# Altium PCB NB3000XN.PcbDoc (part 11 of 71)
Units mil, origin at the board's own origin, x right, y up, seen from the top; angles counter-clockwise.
Board outline 9527.56 x 6929.77 mil, 6 copper layers (Top Layer, GND+SHIELD, MidLayer1, MidLayer2, P2 - 3V3+5V0, Bottom Layer), stack 62.375 mil thick; 832 components, 1027 nets, 4655 pads, 4981 vias.
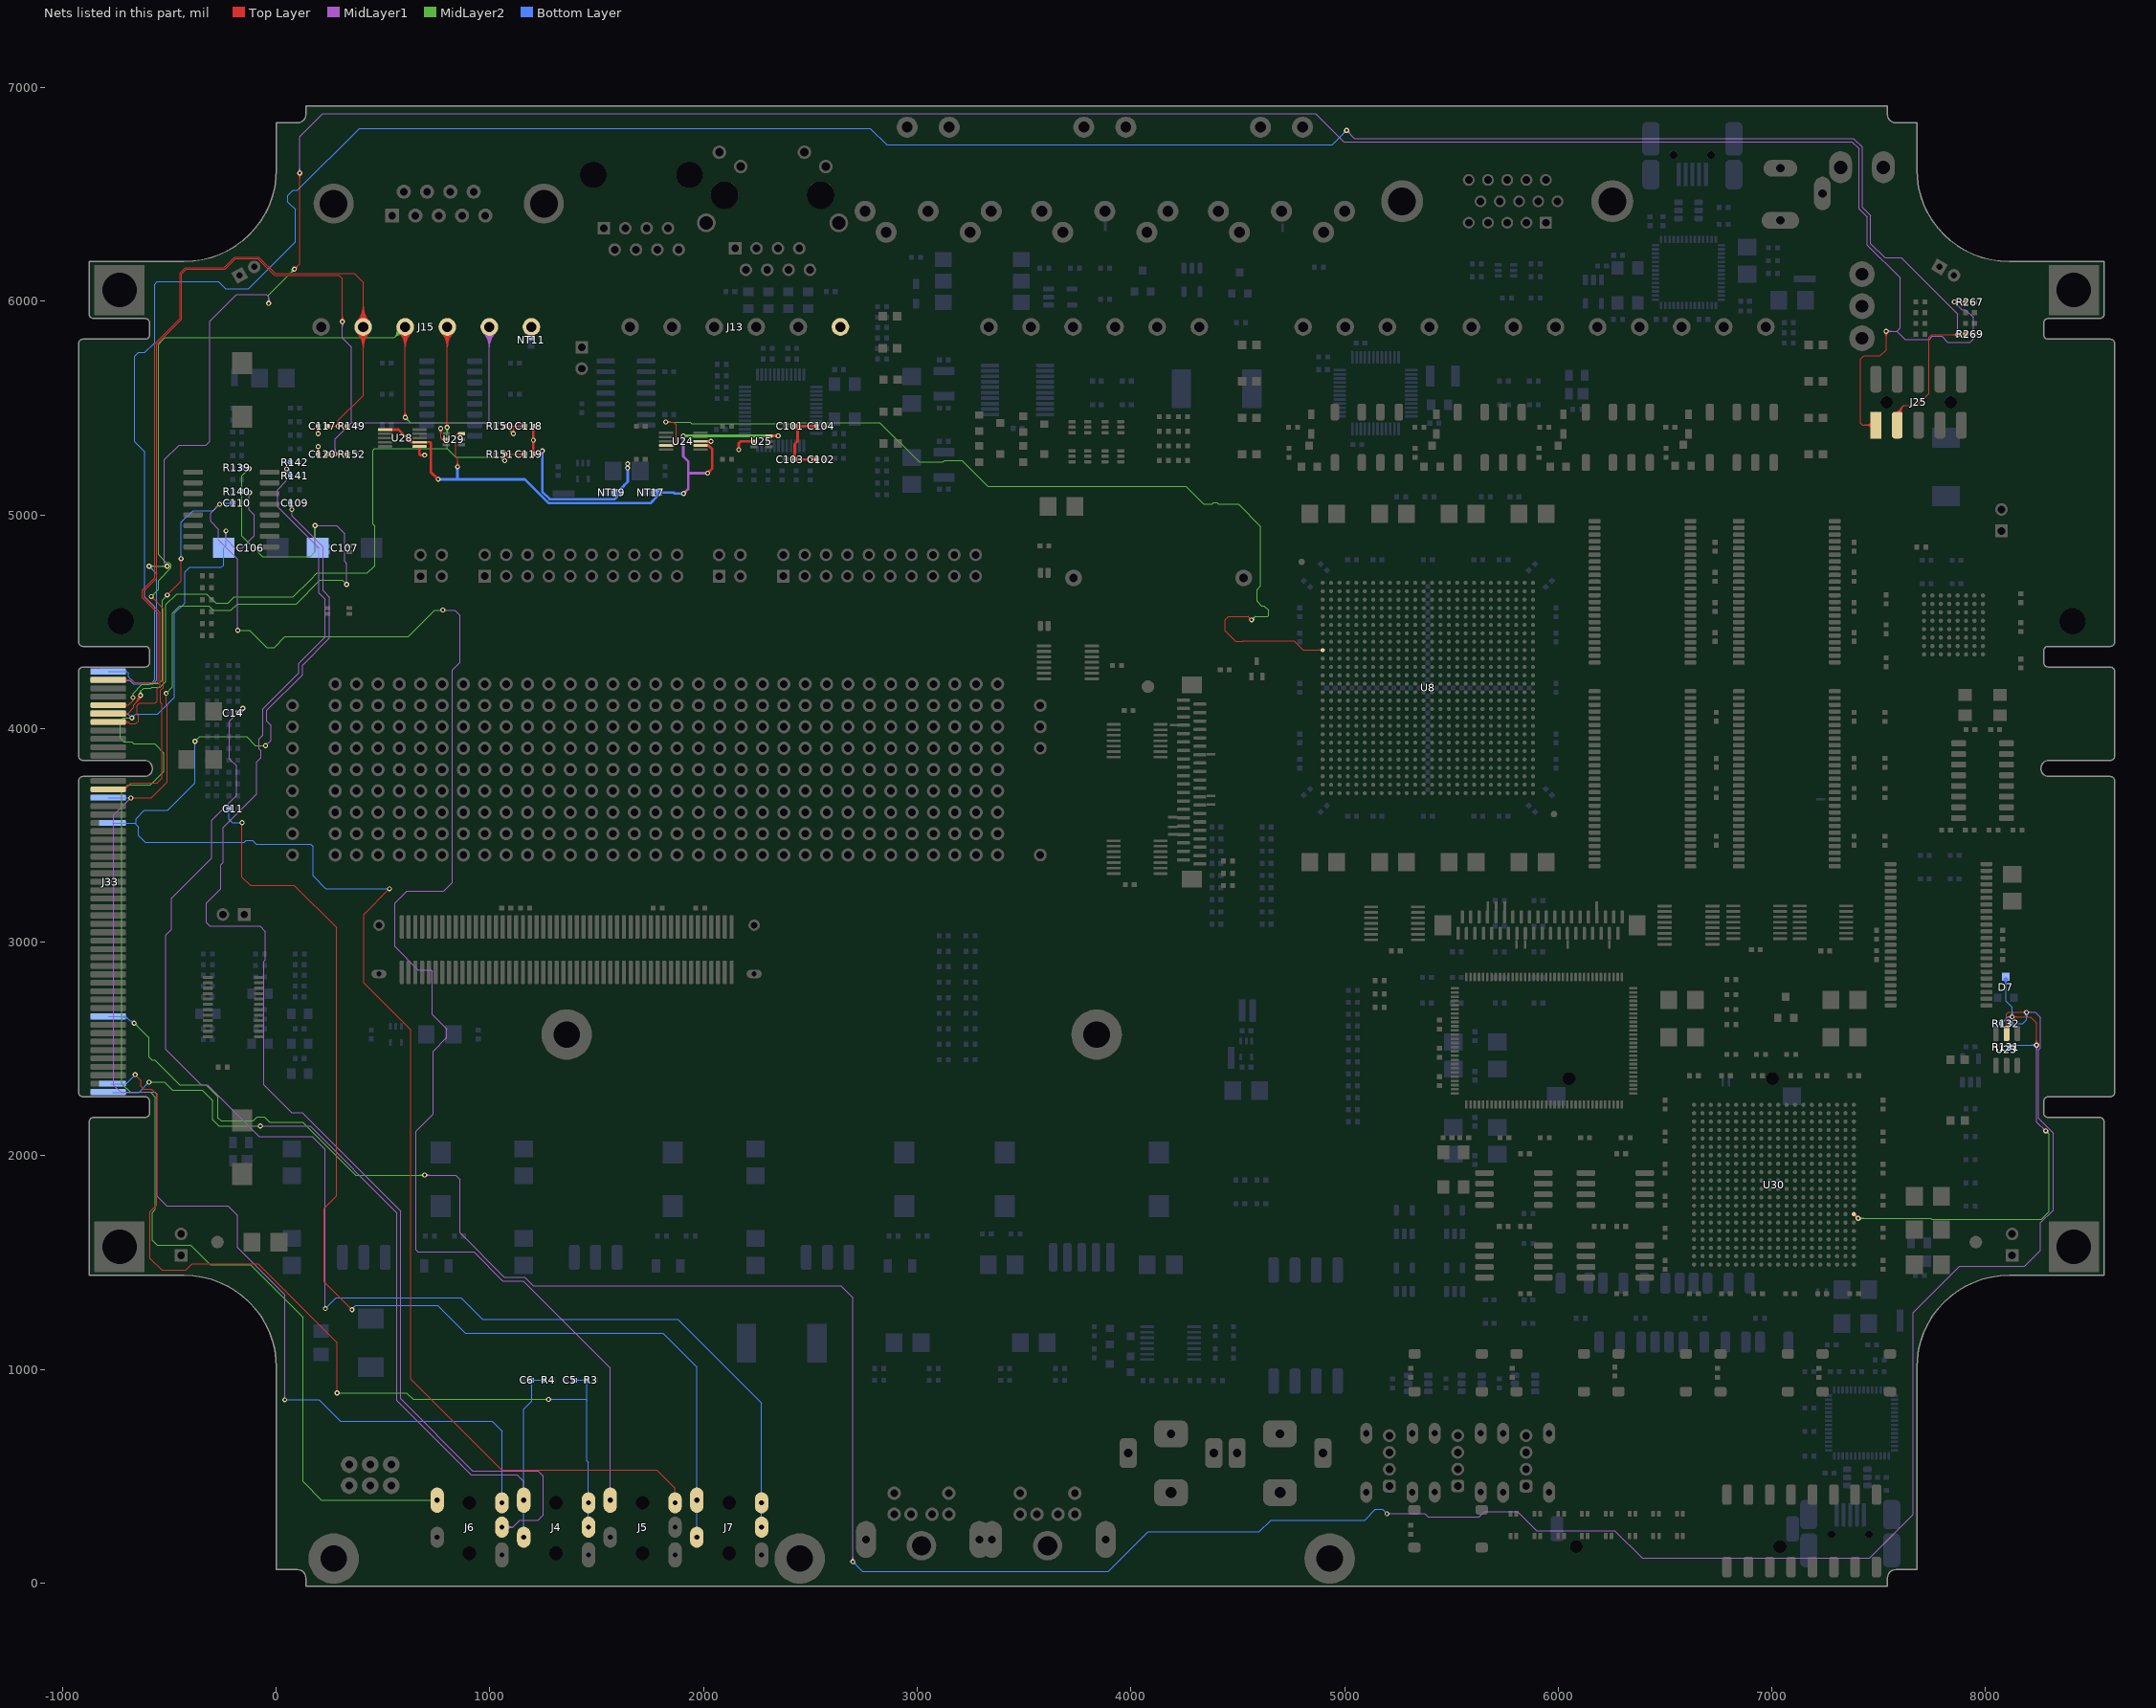
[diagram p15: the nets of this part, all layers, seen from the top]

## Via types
v1: diameter 23, hole 11.81, Top Layer to Bottom Layer, 3672 vias
v2: diameter 26, hole 11.81, Top Layer to Bottom Layer, 461 vias
v3: diameter 19, hole 11.81, Top Layer to Bottom Layer, tented both sides, 396 vias
v4: diameter 23.62, hole 11.81, Top Layer to Bottom Layer, 288 vias
v5: diameter 20, hole 11.81, Top Layer to Bottom Layer, 91 vias
v6: diameter 23, hole 11.81, Top Layer to Bottom Layer, tented both sides, 50 vias
v7: diameter 31, hole 11.81, Top Layer to Bottom Layer, 15 vias
v8: diameter 27.56, hole 11.81, Top Layer to Bottom Layer, tented both sides, 4 vias
v9: diameter 29, hole 11.81, Top Layer to Bottom Layer, 3 vias
v10: diameter 21, hole 11.81, Top Layer to Bottom Layer, 1 vias

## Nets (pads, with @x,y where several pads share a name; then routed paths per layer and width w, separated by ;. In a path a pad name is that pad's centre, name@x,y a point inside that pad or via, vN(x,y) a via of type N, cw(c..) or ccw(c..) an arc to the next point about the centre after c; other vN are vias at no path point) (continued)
ADC.DOUT: U8.J1 U24.9 | length 4725.1
  Top Layer w4: v1(1823.52,5435.04) 1858.15,5435.04 1873.52,5419.67 1873.52,5335.31 1863.52,5325.31 U24.9@1824.29,5325.31 ; v1@1827.41,5431.15 cw(c1836.8,5421.76) 1836.8,5435.04 cw(c1836.8,5448.32) v1@1827.41,5438.93 ; v1@1830.24,5428.32 cw(c1846.46,5412.11) 1846.46,5435.04 cw(c1846.46,5457.98) v1@1830.24,5441.76 ; U24.9@1854.58,5322.49 cw(c1861.41,5315.66) 1861.41,5325.31 cw(c1861.41,5334.97) U24.9@1854.58,5328.14 ; v1@4555.69,4508.37 ccw(c4532.76,4508.37) 4548.97,4524.59 ccw(c4565.19,4540.81) v1@4565.19,4517.87 ; v1@4559.69,4508.37 ccw(c4546.41,4508.37) 4555.8,4517.76 ccw(c4565.19,4527.15) v1@4565.19,4513.87 ; v1(4565.19,4508.37) 4548.52,4525.04 4456.86,4525.04 4440.19,4508.37 4440.19,4458.37 4491.19,4407.37 4522.86,4407.37 4523.52,4408.04 4525.35,4409.87 4764.07,4409.87 4806.78,4367.17 4860,4367.17 4870,4367.17 U8.J1@4897.87,4367.17 ; U8.J1@4892.57,4361.86 ccw(c4879.77,4349.06) 4879.77,4367.17 ccw(c4879.77,4385.27) U8.J1@4892.57,4372.47 ; U8.J1@4892.68,4361.97 ccw(c4880.15,4349.44) 4880.15,4367.17 ccw(c4880.15,4384.89) U8.J1@4892.68,4372.36
  MidLayer2 w4: v1@1823.52,5433.37 v1(1823.52,5435.04) 1937.77,5435.04 1945,5427.81 2444.72,5427.81 2449.45,5432.54 2824.97,5432.54 3010.51,5247 3120.29,5247 3128.29,5255 3210,5255 3331.63,5133.37 4256.86,5133.37 4340.19,5050.04 4380.29,5050.04 4387.75,5057.5 4402.25,5057.5 4409.71,5050.04 4503.65,5050.04 4606.86,4946.83 4606.86,4667.71 4590.19,4651.04 4590.19,4597.37 4612.52,4575.04 4623.52,4575.04 4645.19,4553.37 4645.19,4530.23 4640,4525.04 4581.86,4525.04 v1(4565.19,4508.37) ; v1@1827.41,5431.15 cw(c1836.8,5421.76) 1836.8,5435.04 cw(c1836.8,5448.32) v1@1827.41,5438.93 ; v1@1830.24,5428.32 cw(c1846.46,5412.11) 1846.46,5435.04 cw(c1846.46,5457.98) v1@1830.24,5441.76 ; v1@4565.19,4513.87 ccw(c4565.19,4527.15) 4574.58,4517.76 ccw(c4583.97,4508.37) v1@4570.69,4508.37 ; v1@4565.19,4517.87 ccw(c4565.19,4540.81) 4581.41,4524.59 ccw(c4597.63,4508.37) v1@4574.69,4508.37
ADCDAC_3V3: NT17.1 U24.2 U25.6 U28.1 U28.7 U29.6 | length 3378
  Top Layer w4: v1@841.81,5231.76 ccw(c825.59,5247.98) 848.52,5247.98 ccw(c871.46,5247.98) v1@855.24,5231.76 ; v1@844.64,5228.93 ccw(c835.25,5238.32) 848.52,5238.32 ccw(c861.8,5238.32) v1@852.41,5228.93 ; v1(848.52,5225.04) 848.52,5266.67 840.19,5275 840.19,5372 848.19,5380 ; U29.6@854.04,5376.81 ccw(c848.19,5373.03) 848.19,5380 ; U29.6@854.04,5383.19 cw(c848.19,5386.96) 848.19,5380 ; U29.6@867.83,5380 848.19,5380
  Top Layer w12: U28.1@509.29,5399.37 572.8,5399.37 631.86,5340.31 U28.7@670.71,5340.31 719.69,5340.31 723.52,5336.48 723.52,5201.04 v1(757.86,5166.71) ; 623.81,5348.37 ccw(c643.24,5367.81) U28.7@643.24,5340.32 ; v1@752.36,5166.71 ccw(c739.08,5166.71) 748.47,5176.1 ccw(c757.86,5185.49) v1@757.86,5172.21 ; U24.2@1985.71,5325.31 2023.84,5325.31 2040,5309.15 2040,5216.52 v1(2019.19,5195.71) ; v1@2019.19,5201.21 ccw(c2019.19,5214.49) 2028.58,5205.1 ccw(c2037.97,5195.71) v1@2024.69,5195.71 ; 2029.17,5319.98 ccw(c2015.84,5306.65) 2013.17,5325.31 cw(c2013.17,5299.56) 2031.38,5317.77 ; U25.6@2307.83,5370 v4(2350,5370) ; v4@2345.89,5365.89 ccw(c2335.97,5355.97) 2335.97,5370 ccw(c2335.97,5384.03) v4@2345.89,5374.11
  MidLayer1 w12: v4@1900.89,5365.89 cw(c1890.97,5355.97) 1905,5355.97 cw(c1919.03,5355.97) v4@1909.11,5365.89 ; v4(1905,5370) 1905,5273.97 1928.36,5250.61 1928.36,5121.54 v1(1906.86,5100.04) ; v1@1906.86,5105.54 ccw(c1906.86,5118.82) 1916.25,5109.43 ccw(c1925.64,5100.04) v1@1912.36,5100.04 ; 1929.06,5195.71 v1(2019.19,5195.71) ; v1@2015.3,5191.82 ccw(c2005.91,5182.43) 2005.91,5195.71 ccw(c2005.91,5208.99) v1@2015.3,5199.6
  MidLayer2 w12: v4(1905,5370) v4(2350,5370) ; v4@1909.11,5365.89 cw(c1919.03,5355.97) 1919.03,5370 cw(c1919.03,5384.03) v4@1909.11,5374.11 ; v4@2345.89,5365.89 ccw(c2335.97,5355.97) 2335.97,5370 ccw(c2335.97,5384.03) v4@2345.89,5374.11
  Bottom Layer w12: v1(757.86,5166.71) 848.52,5166.71 ; v1@761.75,5162.82 cw(c771.14,5153.43) 771.14,5166.71 cw(c771.14,5179.99) v1@761.75,5170.6 ; v1@844.64,5221.15 cw(c835.25,5211.76) 848.52,5211.76 cw(c861.8,5211.76) v1@852.41,5221.15 ; v1(848.52,5225.04) 848.52,5166.71 ; NT17.1@1773.56,5097.98 cw(c1760.44,5083.38) 1780.08,5083.38 ; NT17.1@1786.59,5097.98 ccw(c1799.72,5083.38) 1780.08,5083.38 ; NT17.1@1797.22,5098.34 cw(c1813.86,5081.7) 1813.86,5105.24 cw(c1813.86,5128.77) NT17.1@1797.22,5112.13 ; v1@1902.97,5096.15 ccw(c1893.58,5086.76) 1893.58,5100.04 ccw(c1893.58,5113.32) v1@1902.97,5103.93 ; v1(1906.86,5100.04) 1864.96,5100.04 1859.76,5105.24 NT17.1@1780.08,5105.24 1780.08,5083.37 ; 848.52,5166.71 1163.29,5166.71 1275,5055 1751.7,5055 1780.08,5083.37
AGND: C101.2 C102.2 C103.2 C104.2 C117.2 C118.2 C119.2 C120.2 J13.6 J15.6 NT11.1 NT19.1 U24.3 U25.2 U28.6 U29.2 | length 2383.2
  Top Layer w4: C120.2@189.39,5291.94 ccw(c172.64,5308.69) 196.33,5308.69 ccw(c220.02,5308.68) C120.2@203.27,5291.94 ; C117.2@189.39,5408.06 cw(c172.64,5391.31) 196.33,5391.31 cw(c220.02,5391.32) C117.2@203.27,5408.06 ; v1@189.61,5313.28 cw(c173.4,5297.06) 196.33,5297.06 cw(c219.27,5297.06) v1@203.05,5313.28 ; v1@189.61,5386.72 ccw(c173.4,5402.93) 196.33,5402.93 ccw(c219.27,5402.93) v1@203.05,5386.72 ; C120.2@192.22,5289.11 ccw(c182.3,5299.03) 196.33,5299.03 ccw(c210.36,5299.03) C120.2@200.44,5289.11 ; C117.2@192.22,5410.89 cw(c182.3,5400.97) 196.33,5400.97 cw(c210.36,5400.97) C117.2@200.44,5410.89 ; v1@192.44,5316.11 cw(c183.05,5306.72) 196.33,5306.72 cw(c209.61,5306.72) v1@200.22,5316.11 ; v1@192.44,5383.89 ccw(c183.05,5393.28) 196.33,5393.28 ccw(c209.61,5393.28) v1@200.22,5383.89 ; C120.2@196.33,5285 v1(196.33,5320) ; v1(196.33,5380) C117.2@196.33,5415 ; v1@763.28,5398.28 cw(c747.06,5382.06) 770,5382.06 cw(c792.93,5382.06) v1@776.72,5398.28 ; v1@766.11,5401.11 cw(c756.72,5391.72) 770,5391.72 cw(c783.28,5391.72) v1@773.89,5401.11 ; v1(770,5405) 770,5360 775.59,5354.41 ; U29.2@780.19,5354.41 U29.2@795,5354.41 775.59,5354.41 ; U29.2@781.15,5351.32 ccw(c775.59,5347.87) 775.59,5354.41 ; U29.2@781.15,5357.5 cw(c775.59,5360.95) 775.59,5354.41 ; C104.2@2530.2,5415 C104.2@2531.86,5416.66
  Top Layer w12: U28.6@670.71,5320.63 670.71,5304.29 670.71,5284.29 675,5280 v1(695,5280) ; v1@691.11,5276.11 ccw(c681.72,5266.72) 681.72,5280 ccw(c681.72,5293.28) v1@691.11,5283.89 ; C119.2@1199.56,5289.11 ccw(c1189.64,5299.03) 1203.67,5299.03 ccw(c1217.7,5299.03) 1207.78,5289.11 ccw(c1217.7,5299.03) 1217.7,5285 ccw(c1217.7,5270.97) C119.2@1207.78,5280.89 ; C118.2@1199.56,5410.89 cw(c1189.64,5400.97) 1203.67,5400.97 cw(c1217.7,5400.97) C118.2@1207.78,5410.89 ; C118.2@1203.67,5415 C119.2@1203.67,5285 1230.48,5285 v1(1245.52,5300.04) ; U24.3@1985.71,5345 v4(2035,5345) ; v4@2030.89,5340.89 ccw(c2020.97,5330.97) 2020.97,5345 ccw(c2020.97,5359.03) v4@2030.89,5349.11 ; v1@2161.11,5308.89 ccw(c2151.72,5318.28) 2165,5318.28 ccw(c2178.28,5318.28) v1@2168.89,5308.89 ; v1(2165,5305) 2165,5335 2174.41,5344.41 U25.2@2235,5344.41 ; C103.2@2425,5260 2425.19,5259.81 C103.2@2426.54,5259.81 ; C103.2@2430.64,5255.89 cw(c2440.1,5246.43) 2440.1,5259.81 ; C103.2@2430.64,5264.11 ccw(c2441.02,5274.49) 2441.02,5259.81 ; C101.2@2430.64,5410.89 cw(c2440.56,5400.97) 2440.56,5415 cw(c2440.56,5429.03) C101.2@2430.64,5419.11 ; v1@2495.92,5255.92 ccw(c2486.53,5246.53) 2486.53,5259.81 ccw(c2486.53,5273.09) v1@2495.92,5263.7 ; v1(2499.81,5259.81) C103.2@2426.54,5259.81 ; v1@2499.81,5260 C102.2@2530.2,5260 ; v1@2503.7,5255.92 cw(c2513.55,5246.07) 2513.55,5260 ; v1@2503.7,5263.7 ccw(c2512.63,5272.63) 2512.63,5260 ; C102.2@2526.09,5255.89 ccw(c2516.17,5245.97) 2516.17,5260 ccw(c2516.17,5274.03) C102.2@2526.09,5264.11 ; C104.2@2526.09,5410.89 ccw(c2516.17,5400.97) 2516.17,5415 ccw(c2516.17,5429.03) C104.2@2526.09,5419.11 ; C104.2@2530.2,5415 C101.2@2426.54,5415 2426.54,5411.54 2440,5398.07 2440,5345 2426.54,5331.54 C103.2@2426.54,5260 C103.2@2426.54,5259.81
  Bottom Layer w4: v1@690,5275 v1(695,5280)
  Bottom Layer w12: v1@1241.64,5296.15 cw(c1232.25,5286.76) 1245.52,5286.76 cw(c1258.8,5286.76) v1@1249.41,5296.15 ; v1(1245.52,5300.04) 1245.52,5108.49 1280,5074.02 1583.97,5074.02 1595.08,5085.12 ; NT19.1@1589.04,5097.59 cw(c1579.2,5085.12) 1595.08,5085.12 ; NT19.1@1601.12,5097.59 ccw(c1610.96,5085.12) 1595.08,5085.12 ; NT19.1@1615.08,5105.24 cw(c1663.36,5105.24) 1629.22,5139.38 ; v1@1640.92,5215.92 cw(c1631.07,5206.07) 1645,5206.07 ; v1@1640.92,5223.7 ccw(c1631.07,5233.55) v1@1645,5233.55 ; v1@1640.92,5235.92 cw(c1631.07,5226.07) v1@1645,5226.07 ; 1645,5206.99 cw(c1657.63,5206.99) v1@1648.7,5215.92 ; v1@1645,5226.99 cw(c1657.63,5226.99) v1@1648.7,5235.92 ; v1@1645,5232.63 ccw(c1657.63,5232.63) v1@1648.7,5223.7 ; v1@1645,5240 1645,5239.81 1645,5219.81 1645,5155.16 NT19.1@1595.08,5105.24 1595.08,5085.12
  other v1: 1644.81,5219.81 1644.81,5239.81 1203.67,5350
ATE.AUDIO.AMP_L: C11.2 J7.2 J7.10 | length 5317.2
  Top Layer w4: v1(-159.81,3559.86) -159.81,3305 -121.52,3266.71 83.29,3266.71 281.86,3068.14 281.86,1811.92 225,1755.06 225,1410 v1(355,1280)
  Bottom Layer w4: C11.2@-220.67,3625 -220.67,3574.71 -205.82,3559.86 v1(-159.81,3559.86) ; v1(355,1280) 355,1283.15 371.8,1299.95 755.05,1299.95 885,1170 1810,1170 1968.43,1011.57 J7.2@1968.43,388.03 J7.10@1968.43,214.8
ATE.AUDIO.AMP_R: C14.2 J7.3 J7.11 | length 6360.2
  MidLayer1 w4: v1(-156.5,4095) -218.14,4033.36 -218.14,3858.14 -185,3825 -185,3686.31 -301.31,3570 -301.31,3394.95 -490,3206.26 -490,3060 -517.69,3032.31 -517.69,2499.07 -350.34,2331.71 -321.71,2331.71 -80.92,2090.92 ; -80.88,2090.92 169.08,2090.92 230,2030 v1(230,1285)
  Bottom Layer w4: C14.2@-179.33,4073.18 -165,4073.18 ; C14.2@-170.18,4069.63 cw(c-165,4067.62) -165,4073.18 ; C14.2@-170.18,4076.73 ccw(c-165,4078.74) -165,4073.18 ; v1(-156.5,4095) -156.5,4081.68 -165,4073.18 ; v1(230,1285) 280,1335 865,1335 965,1235 1880,1235 2271.57,843.43 J7.3@2271.57,376.22 J7.11@2271.57,262.05
ATE.AUDIO.HP_L: C106.2 J6.2 J33.B6 R140.2 | length 7029.9
  MidLayer1 w4: v1(-235,4925) -235,4887.05 -193.47,4845.52 -159.48,4845.52 -101.48,4903.52 -101.48,5000 -126.48,5025 -126.48,5103.52 v1(-125,5105)
  MidLayer2 w4: v1@-678.57,4053.56 v1(-675,4050) -715,4050 -730,4035 -730,3955 -713.88,3938.88 -676.12,3938.88 -666.29,3929.04 -569.04,3929.04 -525,3885 -525,3800 -588,3737 -693,3737 -723,3707 -723,2338 -683,2298 -588,2298 -565,2275 -565,1750 -580,1735 -580,1605 -556.59,1581.59 -399.97,1581.59 -308.38,1490 -120,1490 125,1245 125,475 211.97,388.03 J6.2@753.43,388.03
  Bottom Layer w4: J33.B6@-785.98,4070.18 -695.18,4070.18 v1(-675,4050) -657.69,4067.31 -630,4067.31 ; -648.5,4067.31 -630,4067.31 ; C106.2@-243.14,4848.04 C106.2@-245.91,4845.28 ; v1(-235,4925) -235,4856.18 C106.2@-245.91,4845.28 ; R140.2@-160.85,5110.08 -142.85,5110.08 -136.81,5104.04 -125.96,5104.04 v1(-125,5105) ; -630,4067.31 -555.31,4067.31 -476.5,4146.12 -476.5,4540 -428,4588.5 -428,4732 -405,4755 -255.91,4755 -245.91,4765 C106.2@-245.91,4845.28
ATE.AUDIO.HP_R: C107.2 J6.3 J33.B14 R139.2 | length 8265.3
  Top Layer w4: v1(-680,3675) -584.81,3675 -560.98,3698.83 ; -564.38,3695.43 -510,3749.81 -510,3795 ; v1(-515,4165) -515,4110.19 -509.81,4105 -509.81,4070.19 ; -510,4070 -509.81,4070.19 ; -509.81,3795 -509.81,4070.19
  MidLayer1 w4: v1(-680,3675) -760,3595 -760,2330 -728,2298 -568,2298 -557.02,2287.02 -557.02,1810 -512.02,1765 -225,1765 -180.09,1720.09 -180.09,1570.09 40.19,1349.81 v1(40.19,858.37) ; v1@184.4,4947.5 v1(181.86,4950.04) 281.82,4950.04 320,4911.86 320,4782.05 330,4772.05 v1(330,4675)
  MidLayer2 w4: v1(-515,4165) -484.81,4195.19 -484.81,4540.13 -451.22,4573.71 -316.19,4573.71 -295.85,4553.37 -212.19,4553.37 -181.69,4583.87 93.87,4583.87 204.5,4694.5 310.5,4694.5 v1(330,4675) ; v1(-126.48,5216.71) -160.14,5183.04 -160.14,4900.88 -64.27,4805 160,4805 181.86,4826.86 v1(181.86,4950.04)
  Bottom Layer w4: J33.B14@-785.98,3676.48 -784.5,3675 v1(-680,3675) ; R139.2@-160.85,5220.92 -130.68,5220.92 v1(-126.48,5216.71) ; v1(40.19,858.37) 200,858.37 300,758.37 1010,758.37 1056.57,711.8 J6.3@1056.57,376.22 ; v1(181.86,4950.04) 181.86,4857.51 C107.2@194.09,4845.28
ATE.AUDIO.HP_SENSE: J6.11 R141.1 R142.2 | length 6916.6
  MidLayer1 w4: v1@41.81,5208.99 cw(c25.59,5192.77) 48.52,5192.77 cw(c71.46,5192.77) v1@55.24,5208.99 ; v1@44.64,5211.82 cw(c35.25,5202.43) 48.52,5202.43 cw(c61.8,5202.43) v1@52.41,5211.82 ; v1(48.52,5215.71) 48.52,5160 6.52,5118 6.52,5037.44 200,4843.97 200,4635 230,4605 230,4429.5 147.32,4346.81 105.19,4304.69 105.19,4259.94 -62.5,4092.25 -62.5,3970 -80,3952.5 -80,3904.86 -70.14,3895 -70.14,3864.86 -91.3,3843.7 -91.3,3693.7 -248.81,3536.19 -248.81,3373.2 -259.81,3362.2 -259.81,3250.04 -326.48,3183.37 -326.48,3091.71 -309.81,3075.04 -75,3075.04 -50,3050.04 -50,2917.93 -57.5,2910.43 -57.5,2909.75 -58,2909.25 -58,2331.56 71.06,2202.5 120.43,2202.5 582.5,1740.43 582.5,862.25 919.75,525 1225,525 1250,500 1250,320 1225,295 1140,295 1107.05,262.05 ; J6.11@1056.57,262.05 1107.05,262.05 ; J6.11@1075.3,251.5 cw(c1093.36,241.33) 1093.36,262.05 cw(c1093.36,282.77) J6.11@1075.3,272.6 ; J6.11@1078.79,249.53 cw(c1100.2,237.47) 1100.2,262.05 cw(c1100.2,286.62) J6.11@1078.79,274.56 ; J6.11@1082.27,247.57 cw(c1107.05,233.62) 1107.05,262.05 ; J6.11@1082.27,276.52 ccw(c1107.05,290.48) 1107.05,262.05
  Bottom Layer w4: v1@41.81,5222.43 ccw(c23.17,5241.06) 49.52,5241.06 ; v1@44.64,5219.6 ccw(c32.83,5231.4) 49.52,5231.4 ; v1@48.52,5206.21 cw(c48.52,5183.27) 64.74,5199.49 cw(c80.96,5215.71) v1@58.02,5215.71 ; v1@48.52,5210.21 cw(c48.52,5196.93) 57.91,5206.32 cw(c67.3,5215.71) v1@54.02,5215.71 ; v1(48.52,5215.71) 66.79,5197.44 ; v1@49.52,5216.71 49.52,5243.46 51.86,5245.8 ; 49.52,5236.23 ccw(c69.04,5236.23) v1@55.24,5222.43 ; R141.1@62.8,5191.14 ccw(c59.82,5197.44) 66.79,5197.44 ; R142.2@66.28,5245.8 51.86,5245.8 ; R141.1@66.79,5182.22 66.79,5197.44 ; R141.1@70.78,5191.14 cw(c73.76,5197.44) 66.79,5197.44 ; 51.86,5245.8 cw(c51.86,5239.3) 57.78,5241.97 ccw(c51.86,5239.3) 51.86,5245.8 ; 51.86,5245.8 ccw(c51.86,5252.29) 57.78,5249.62 cw(c51.86,5252.29) 51.86,5245.8
ATE.AUDIO.LIN_L: C6.1 J4.2 J4.10 J33.B49 R4.2 | length 4242.5
  MidLayer1 w4: v1(-74.48,2139.71) 158.48,2139.71 565,1733.18 565,855 912.5,507.5 1127.5,507.5 1158.43,476.57 J4.2@1158.43,388.03
  MidLayer2 w4: v1(-595,2345) -522.62,2345 -485,2307.38 -347.38,2307.38 -297.5,2257.5 -297.5,2170 -267.21,2139.71 v1(-74.48,2139.71)
  Bottom Layer w4: -702.5,2297.5 -765,2297.5 -642.5,2297.5 v1(-595,2345) ; J4.10@1158.43,214.8 J4.2@1158.43,388.03 1158.43,815 1195.67,852.24 C6.1@1195.67,950 R4.2@1253.83,950
ATE.AUDIO.LIN_R: C5.1 J4.3 J4.11 J33.B48 R3.2 | length 4297.5
  Top Layer w4: v1(-660,2380) -633,2353 -633,2325.62 -618.88,2311.5 -585,2311.5 -560,2286.5 -560,1770 -590,1740 -590,1520 -534.71,1464.71 -422.92,1464.71 -392.62,1495 -85,1495 285,1125 v1(285,890)
  MidLayer2 w4: v1(285,890) 610,890 640,860 v1(1275,860)
  Bottom Layer w4: J33.B48@-775,2337.9 J33.B48@-766.3,2337.9 -702.1,2337.9 v1(-660,2380) ; v1(1275,860) 1448.82,860 1453.82,855 ; C5.1@1395.66,950 R3.2@1453.82,950 1453.82,855 ; J4.11@1461.57,262.05 J4.3@1461.57,376.22 1461.57,565 1453.82,572.76 1453.82,855
ATE.AUDIO.LOUT_L: C110.2 J5.2 J33.A5 | length 8411.2
  Top Layer w4: J33.A5@-785.98,4109.55 -691.71,4109.55 ; J33.A5@-711.14,4104.53 cw(c-700.33,4095.4) -700.33,4109.55 cw(c-700.33,4123.71) J33.A5@-711.14,4114.57 ; J33.A5@-708.09,4101.95 cw(c-691.71,4088.12) -691.71,4109.55 ; J33.A5@-708.09,4117.16 ccw(c-691.71,4130.99) -691.71,4109.55 ; v1(-670,4145) -670,4131.27 -691.71,4109.55 ; v1(-509.81,4625.04) -445,4689.85 v1(-445,4795)
  MidLayer1 w4: v1(-265,5050) -306.98,5008.02 -306.98,4969.35 -270.14,4932.52 -270.14,4884.01 -180,4793.86 v1(-180,4460) ; v1@785,4550 v1(780,4555) 835,4555 860,4530 860,4309.75 825,4274.75 825,3280 785.04,3240.04 612.67,3240.04 555.11,3182.48 555.11,2978.61 663.72,2870 725,2870 731.02,2863.98 731.02,2662.39 798.5,2594.92 798.5,2553.48 735.02,2490 735.02,2196.84 654,2115.82 654,1559 663,1550 925,1550 1060,1415 1155,1415 1513.55,1056.45 1563.43,1006.57 J5.2@1563.43,388.03
  MidLayer2 w4: v1(-670,4145) -670,4165 -627.96,4207.04 -592.9,4207.04 -589.63,4210.31 -550.96,4210.31 -533.48,4227.78 -533.48,4601.37 v1(-509.81,4625.04) ; v1(-180,4460) -125,4460 -45,4380 -8.33,4380 41.67,4430 617.63,4430 742.63,4555 v1(780,4555)
  Bottom Layer w4: v1(-445,4795) -445,4965 -390,5020 -295,5020 v1(-265,5050) -259.92,5055.08 C110.2@-202.7,5055.08
ATE.AUDIO.LOUT_R: C109.1 J5.3 J33.B17 | length 7821.7
  Top Layer w4: v1(530,3250) 530,3249.52 410,3129.52 410,2810 630,2590 630,955.57 1055,530.57 1780,530.57 1866.57,443.99 J5.3@1866.57,376.22
  MidLayer1 w4: v1@-45,3925 v1(-50,3920) -25,3945 -25,4015 -45,4035 -45,4085 122.69,4252.69 122.69,4297.44 250,4424.75 250,4615 220,4645 220,4848.71 73.52,4995.19 v1(73.52,5025.04)
  MidLayer2 w4: v1(-380,3940) -358.29,3961.71 -138.63,3961.71 -96.92,3920 v1(-50,3920)
  Bottom Layer w4: J33.B17@-765.61,3557.69 -658.07,3557.69 -655.76,3560 ; v1@-380,3930 -380,3745 -507,3618 -617,3618 -617,3617.35 -655.76,3578.58 -655.76,3560 ; 66.79,5040.28 ccw(c83.5,5040.28) v1@74.35,5026.3 ; C109.1@66.79,5047.68 ccw(c88.35,5047.68) v1@76.54,5029.64 ; v1(73.52,5025.04) 66.79,5031.77 C109.1@66.79,5055.08 ccw(c93.2,5055.08) v1@78.73,5032.99 ; v1@529.99,3250.04 232.15,3250.04 172,3310.19 172,3448.08 161.71,3458.37 -93.65,3458.37 -111.98,3476.71 -140.97,3476.71 -150.18,3467.5 -612.5,3467.5 -645,3500 -645,3540 -655.76,3550.76 -655.76,3560
ATE.DAC#.DAC0: C117.1 J15.2 J33.A2 R149.1 | length 5765.6
  Top Layer w4: J33.A2@-785.98,4227.66 -675.96,4227.66 -665,4216.71 -553.29,4216.71 -552,4218 -552,4538.31 -598.56,4584.87 -598.69,4584.87 -625.81,4612 -625.81,4648.33 -568.14,4706 -568.14,5800.96 -450,5919.1 -450,6133.37 -425,6158.37 -242.94,6158.37 -193.83,6207.48 -82.48,6207.48 -5,6130 365,6130 406.99,6088.01 J15.2@406.99,5880 406.99,5560 290,5443.01 v1(290,5415) ; J33.A2@-711.58,4222.16 cw(c-698.3,4208.88) -698.3,4227.66 cw(c-698.3,4246.45) J33.A2@-711.58,4233.17 ; J33.A2@-708.76,4219.33 cw(c-688.65,4199.23) -688.65,4227.66 cw(c-688.65,4256.1) J33.A2@-708.76,4235.99 ; C117.1@237.67,5415 v1(290,5415) ; C117.1@241.78,5410.89 cw(c251.7,5400.97) 251.7,5415 cw(c251.7,5429.03) C117.1@241.78,5419.11 ; C117.1@244.61,5408.06 cw(c261.36,5391.31) 261.36,5415 cw(c261.36,5438.69) C117.1@244.61,5421.94 ; R149.1@333.82,5415 v1(290,5415) ; J15.2@379.17,5852.18 cw(c312.02,5785.03) 406.99,5785.03 cw(c501.96,5785.03) J15.2@434.8,5852.18 ; J15.2@379.17,5907.82 ccw(c312.02,5974.97) 406.99,5974.97 ccw(c501.96,5974.97) J15.2@434.8,5907.82 ; J15.2@382,5855.01 cw(c321.67,5794.69) 406.99,5794.69 cw(c492.3,5794.69) J15.2@431.98,5855.01 ; J15.2@382,5904.99 ccw(c321.67,5965.31) 406.99,5965.31 ccw(c492.3,5965.31) J15.2@431.98,5904.99 ; J15.2@384.83,5857.84 cw(c331.33,5804.34) 406.99,5804.34 cw(c482.65,5804.34) J15.2@429.15,5857.84 ; J15.2@384.83,5902.16 ccw(c331.33,5955.66) 406.99,5955.66 ccw(c482.65,5955.66) J15.2@429.15,5902.16 ; J15.2@387.66,5860.67 cw(c340.99,5814) 406.99,5814 cw(c472.99,5814) J15.2@426.32,5860.67 ; J15.2@387.66,5899.33 ccw(c340.99,5946) 406.99,5946 ccw(c472.99,5946) J15.2@426.32,5899.33 ; J15.2@390.49,5863.5 cw(c350.64,5823.66) 406.99,5823.66 cw(c463.33,5823.66) J15.2@423.49,5863.5 ; J15.2@390.49,5896.5 ccw(c350.64,5936.34) 406.99,5936.34 ccw(c463.33,5936.34) J15.2@423.49,5896.5 ; J15.2@393.31,5866.33 cw(c360.3,5833.31) 406.99,5833.31 cw(c453.68,5833.31) J15.2@420.66,5866.33 ; J15.2@393.31,5893.67 ccw(c360.3,5926.69) 406.99,5926.69 ccw(c453.68,5926.69) J15.2@420.66,5893.67 ; 267.06,5415 cw(c267.06,5392.06) 283.28,5408.28 ccw(c267.06,5392.06) 267.06,5415 ; 267.06,5415 ccw(c267.06,5437.93) v1@283.28,5421.72 ; 267.06,5415 ccw(c267.06,5437.93) v1@283.28,5421.72 ; 276.72,5415 cw(c276.72,5401.72) 286.11,5411.11 ccw(c276.72,5401.72) 276.72,5415 ; 276.72,5415 ccw(c276.72,5428.28) v1@286.11,5418.89 ; 276.72,5415 ccw(c276.72,5428.28) v1@286.11,5418.89 ; v1@283.28,5421.72 ccw(c267.06,5437.93) 290,5437.93 ccw(c312.93,5437.93) v1@296.72,5421.72 ; v1@286.11,5418.89 ccw(c276.72,5428.28) 290,5428.28 ccw(c303.28,5428.28) v1@293.89,5418.89 ; v1@293.89,5418.89 ccw(c303.28,5428.28) 303.28,5415 ; v1@293.89,5418.89 ccw(c303.28,5428.28) 303.28,5415 ; v1@296.72,5421.72 ccw(c312.93,5437.93) 312.93,5415 ; v1@296.72,5421.72 ccw(c312.93,5437.93) 312.93,5415 ; 303.28,5415 ccw(c303.28,5401.72) 293.89,5411.11 cw(c303.28,5401.72) 303.28,5415 ; 312.93,5415 ccw(c312.93,5392.06) 296.72,5408.28 cw(c312.93,5392.06) 312.93,5415
ATE.DAC#.DAC1: C118.1 J15.3 J33.A13 R150.1 | length 6280.2
  Top Layer w4: J33.A13@-785.98,3715.85 -709.15,3715.85 -680,3745 -556.52,3745 -534.5,3767.02 -534.5,4115 -541,4121.5 -541,4179 -528,4192 -528,4561.56 v1(-584.81,4618.37) ; J33.A13@-717.08,3715.63 ccw(c-717.08,3734.26) J33.A13@-703.91,3721.09 ; J33.A13@-717.08,3719.63 ccw(c-717.08,3747.92) -697.08,3727.92 ; J33.A13@-717.08,3723.63 ccw(c-717.08,3761.58) -690.25,3734.75 ; J33.A13@-717.08,3727.63 ccw(c-717.08,3775.23) -683.43,3741.57 ; J33.A13@-705.3,3715.85 cw(c-696.03,3715.85) -702.59,3722.41 ; v1@-584.81,4608.87 cw(c-584.81,4585.94) -568.59,4602.16 cw(c-552.37,4618.37) v1@-575.31,4618.37 ; v1@-584.81,4612.87 cw(c-584.81,4599.6) -575.42,4608.99 cw(c-566.03,4618.37) v1@-579.31,4618.37 ; J15.3@576.02,5852.18 cw(c508.87,5785.03) 603.84,5785.03 cw(c698.81,5785.03) J15.3@631.66,5852.18 ; J15.3@578.85,5855.01 cw(c518.52,5794.69) 603.84,5794.69 cw(c689.15,5794.69) J15.3@628.83,5855.01 ; J15.3@581.68,5857.84 cw(c528.18,5804.34) 603.84,5804.34 cw(c679.5,5804.34) J15.3@626,5857.84 ; J15.3@584.51,5860.67 cw(c537.84,5814) 603.84,5814 cw(c669.84,5814) J15.3@623.17,5860.67 ; J15.3@587.34,5863.5 cw(c547.49,5823.66) 603.84,5823.66 cw(c660.18,5823.66) J15.3@620.34,5863.5 ; J15.3@590.16,5866.33 cw(c557.15,5833.31) 603.84,5833.31 cw(c650.53,5833.31) J15.3@617.51,5866.33 ; v4@596.9,5463.1 ccw(c580.15,5479.85) 603.84,5479.85 ccw(c627.52,5479.85) v4@610.78,5463.1 ; v4@599.73,5460.27 ccw(c589.81,5470.19) 603.84,5470.19 ccw(c617.87,5470.19) v4@607.95,5460.27 ; v4(603.84,5456.16) J15.3@603.84,5880 ; R150.1@1070,5415 1110,5415 ; R150.1@1073.76,5411.24 cw(c1082.84,5402.16) 1082.84,5415 cw(c1082.84,5427.84) R150.1@1073.76,5418.76 ; R150.1@1076.59,5408.41 cw(c1092.5,5392.5) 1092.5,5415 cw(c1092.5,5437.5) R150.1@1076.59,5421.59 ; v1@1103.28,5386.72 ccw(c1087.06,5402.93) 1110,5402.93 ccw(c1132.93,5402.93) v1@1116.72,5386.72 ; v1@1106.11,5383.89 ccw(c1096.72,5393.28) 1110,5393.28 ccw(c1123.28,5393.28) v1@1113.89,5383.89 ; v1(1110,5380) 1110,5415 ; C118.1@1155.39,5408.06 ccw(c1138.64,5391.31) 1138.64,5415 ccw(c1138.64,5438.69) C118.1@1155.39,5421.94 ; C118.1@1158.22,5410.89 ccw(c1148.3,5400.97) 1148.3,5415 ccw(c1148.3,5429.03) C118.1@1158.22,5419.11 ; C118.1@1162.33,5415 1110,5415
  MidLayer2 w4: v1(-584.81,4618.37) -551.48,4651.71 -551.48,4693.34 -492.19,4752.62 -492.19,4767.38 -502.62,4777.81 -516.5,4777.81 -551.48,4812.79 -551.48,5800 -521.48,5830 553.84,5830 ; v1@-584.81,4623.87 ccw(c-584.81,4637.15) -575.42,4627.76 ccw(c-566.03,4618.37) v1@-579.31,4618.37 ; v1@-584.81,4627.87 ccw(c-584.81,4650.81) -568.59,4634.59 ccw(c-552.37,4618.37) v1@-575.31,4618.37 ; J15.3@565.54,5871.03 cw(c522.81,5861.03) 553.84,5830 ; J15.3@569.43,5871.94 cw(c531.05,5862.96) 558.92,5835.09 cw(c586.8,5807.21) J15.3@595.78,5845.59 ; J15.3@573.33,5872.85 cw(c539.29,5864.89) 564.01,5840.17 cw(c588.72,5815.45) J15.3@596.69,5849.49 ; J15.3@577.22,5873.77 cw(c547.53,5866.81) 569.09,5845.25 cw(c590.65,5823.69) J15.3@597.61,5853.38 ; J15.3@581.11,5874.68 cw(c555.77,5868.74) 574.18,5850.34 cw(c592.58,5831.93) J15.3@598.52,5857.28 ; J15.3@594.87,5841.7 ccw(c584.87,5798.98) 553.84,5830 ; v4@603.84,5446.35 cw(c603.84,5422.66) 620.59,5439.41 cw(c637.34,5456.16) v4@613.65,5456.16 ; v4@603.84,5450.35 cw(c603.84,5436.32) 613.76,5446.24 cw(c623.68,5456.16) v4@609.65,5456.16 ; v4(603.84,5456.16) 627.5,5432.5 1057.49,5432.5 1063.76,5426.23 v1(1110,5380) ; J15.3@603.84,5880 553.84,5830 ; v1@1100.5,5380 ccw(c1077.56,5380) 1093.78,5396.22 ccw(c1110,5412.43) v1@1110,5389.5 ; v1@1104.5,5380 ccw(c1091.22,5380) 1100.61,5389.39 ccw(c1110,5398.78) v1@1110,5385.5
ATE.DAC#.DAC2: C119.1 J15.4 J33.A6 R151.1 | length 4976.3
  Top Layer w4: J33.A6@-785.98,4070.18 -694.82,4070.18 ; J33.A6@-710.65,4065.81 cw(c-702.38,4060.17) -702.38,4070.18 cw(c-702.38,4080.19) J33.A6@-710.65,4074.56 ; J33.A6@-707.35,4063.56 cw(c-694.82,4055.03) -694.82,4070.18 ; J33.A6@-707.35,4076.81 ccw(c-694.82,4085.34) -694.82,4070.18 ; -659.07,4117.45 ccw(c-694.34,4152.72) v1@-644.49,4154.64 ; -652.59,4123.92 ccw(c-681.87,4153.2) v1@-640.5,4154.79 ; -646.12,4130.4 ccw(c-669.4,4153.68) v1@-636.5,4154.94 ; -639.64,4136.87 ccw(c-656.93,4154.16) v1@-632.5,4155.1 ; v1(-635,4155) -635,4141.52 -665.81,4110.71 -665.81,4099.19 -694.82,4070.18 ; J15.4@772.87,5852.18 cw(c705.72,5785.03) 800.69,5785.03 cw(c895.66,5785.03) J15.4@828.51,5852.18 ; J15.4@775.7,5855.01 cw(c715.37,5794.69) 800.69,5794.69 cw(c886,5794.69) J15.4@825.68,5855.01 ; J15.4@778.53,5857.84 cw(c725.03,5804.34) 800.69,5804.34 cw(c876.35,5804.34) J15.4@822.85,5857.84 ; J15.4@781.36,5860.67 cw(c734.69,5814) 800.69,5814 cw(c866.69,5814) J15.4@820.02,5860.67 ; J15.4@784.19,5863.5 cw(c744.34,5823.66) 800.69,5823.66 cw(c857.03,5823.66) J15.4@817.19,5863.5 ; J15.4@787.01,5866.33 cw(c754,5833.31) 800.69,5833.31 cw(c847.38,5833.31) J15.4@814.36,5866.33 ; v4@793.06,5416.94 ccw(c774.65,5435.35) 800.69,5435.35 ; v4@795.89,5414.11 ccw(c784.31,5425.69) 800.69,5425.69 ; v4@800.69,5410.69 J15.4@800.69,5880 ; 800.69,5422.37 ccw(c812.37,5422.37) v4@804.11,5414.11 ; 800.69,5432.02 ccw(c822.02,5432.02) v4@806.94,5416.94 ; v1@1063.14,5260.43 ccw(c1046.58,5276.99) R151.1@1070,5276.99 ; R151.1@1063.41,5277.92 cw(c1047.5,5262.01) 1070,5262.01 cw(c1092.5,5262.01) R151.1@1076.59,5277.92 ; v1@1065.97,5257.6 ccw(c1056.23,5267.33) 1070,5267.33 ; R151.1@1066.24,5280.75 cw(c1057.16,5271.67) 1070,5271.67 cw(c1082.84,5271.67) R151.1@1073.76,5280.75 ; v1@1070,5253.71 R151.1@1070,5285 C119.1@1162.33,5285 ; 1070,5266.64 ccw(c1082.79,5266.64) v1@1073.75,5257.6 ; R151.1@1070,5276.3 ccw(c1092.45,5276.3) v1@1076.57,5260.43 ; R151.1@1073.76,5281.24 cw(c1082.84,5272.16) 1082.84,5285 cw(c1082.84,5297.84) R151.1@1073.76,5288.76 ; R151.1@1076.59,5278.41 cw(c1092.5,5262.5) 1092.5,5285 cw(c1092.5,5307.5) R151.1@1076.59,5291.59 ; C119.1@1155.39,5278.06 ccw(c1138.65,5261.31) 1138.65,5285 ccw(c1138.64,5308.69) C119.1@1155.39,5291.94 ; C119.1@1158.22,5280.89 ccw(c1148.3,5270.97) 1148.3,5285 ccw(c1148.3,5299.03) C119.1@1158.22,5289.11
  MidLayer2 w4: v1@-641.07,4162.31 ccw(c-651.83,4175.25) -635,4175.25 ; v1@-638.52,4159.23 ccw(c-644.75,4166.72) -635,4166.72 ccw(c-625.25,4166.72) v1@-631.48,4159.23 ; v1(-635,4155) -635,4175.25 ; v1@-628.93,4162.31 cw(c-618.17,4175.25) -635,4175.25 ; v4@793.06,5403.06 cw(c776.31,5386.31) 800,5386.31 cw(c823.69,5386.31) v4@806.94,5403.06 ; v4@795.89,5405.89 cw(c785.97,5395.97) 800,5395.97 cw(c814.03,5395.97) v4@804.11,5405.89 ; v4(800,5410) 800,5310 ; v1@1060.36,5253.71 ccw(c1037.42,5253.71) 1053.64,5269.93 ccw(c1069.86,5286.14) v1@1069.86,5263.21 ; v1@1064.36,5253.71 ccw(c1051.08,5253.71) 1060.47,5263.1 ccw(c1069.86,5272.49) v1@1069.86,5259.21 ; v1(1069.86,5253.71) 1053.56,5270 840,5270 800,5310 ; -635,4175.25 -620.71,4189.54 -585.65,4189.54 -582.38,4192.81 -543.71,4192.81 -515.98,4220.54 -515.98,4580.08 -465.56,4630.5 -325.6,4630.5 -281.97,4586.87 -226.26,4586.87 -195.76,4617.37 80,4617.37 160.9,4698.27 190.62,4728 426.69,4728 461.5,4762.81 461.5,4947.19 452,4956.69 452,5302 460,5310 800,5310
ATE.DAC#.DAC3: C120.1 J15.5 J33.A7 R152.1 | length 6441.9
  Top Layer w4: J33.A7@-785.98,4030.81 -691.8,4030.81 ; J33.A7@-711.13,4025.81 cw(c-700.38,4016.78) -700.38,4030.81 cw(c-700.38,4044.85) J33.A7@-711.13,4035.82 ; J33.A7@-708.07,4023.24 cw(c-691.8,4009.56) -691.8,4030.81 ; J33.A7@-708.07,4038.39 ccw(c-691.8,4052.06) -691.8,4030.81 ; -595.37,4592.87 -610.32,4607.82 -617.81,4615.31 -617.81,4645.02 -559.81,4703.02 -559.81,5797.98 -459.81,5897.98 -442,5915.79 -442,6128 -420,6150 -290,6150 -239.96,6150.04 -225,6165 -190.52,6199.48 -85.79,6199.48 -8.31,6122 293,6122 310,6105 v4(310,5905) ; -595.25,4592.87 -544,4541.63 -544,4200 -557,4187 -557,4128.5 -565,4120.5 -639,4120.5 -651,4108.5 -651,4064.87 -645,4058.87 -645,4035 -657,4023 -683.98,4023 -691.8,4030.81 ; C120.1@237.67,5285 R152.1@333.82,5285 ; C120.1@241.78,5280.89 cw(c251.7,5270.97) 251.7,5285 ; C120.1@241.78,5289.11 ccw(c251.7,5299.03) 251.7,5285 ; C120.1@244.61,5278.06 cw(c261.35,5261.31) 261.35,5285 cw(c261.36,5308.69) C120.1@244.61,5291.94 ; v1@268.28,5278.28 ccw(c252.07,5262.06) 252.06,5285 ccw(c252.06,5307.93) v1@268.28,5291.72 ; v1@271.11,5281.11 ccw(c261.72,5271.72) 261.72,5285 ccw(c261.72,5298.28) v1@271.11,5288.89 ; v1@278.89,5281.11 cw(c288.28,5271.72) 288.28,5285 cw(c288.28,5298.28) v1@278.89,5288.89 ; v1@281.72,5278.28 cw(c297.93,5262.06) 297.93,5285 cw(c297.94,5307.93) v1@281.72,5291.72 ; v4@303.06,5911.94 ccw(c286.31,5928.69) 310,5928.69 ccw(c333.69,5928.69) v4@316.94,5911.94 ; v4@305.89,5909.11 ccw(c295.97,5919.03) 310,5919.03 ccw(c324.03,5919.03) v4@314.11,5909.11 ; R152.1@327.23,5278.41 ccw(c311.32,5262.5) 311.32,5285 ccw(c311.32,5307.5) R152.1@327.23,5291.59 ; R152.1@330.06,5281.24 ccw(c320.98,5272.16) 320.98,5285 ccw(c320.98,5297.84) R152.1@330.06,5288.76
  MidLayer1 w4: v1@268.28,5291.72 ccw(c252.06,5307.93) 275,5307.93 ccw(c297.93,5307.93) v1@281.72,5291.72 ; v1@271.11,5288.89 ccw(c261.72,5298.28) 275,5298.28 ccw(c288.28,5298.28) v1@278.89,5288.89 ; v1(275,5285) 275,5355 352.5,5432.5 ; v4@303.06,5898.06 cw(c286.31,5881.31) 310,5881.31 cw(c333.69,5881.31) v4@316.94,5898.06 ; v4@305.89,5900.89 cw(c295.97,5890.97) 310,5890.97 cw(c324.03,5890.97) v4@314.11,5900.89 ; v4(310,5905) 310,5827.5 352.5,5785 352.5,5432.5 ; J15.5@969.72,5852.18 cw(c902.57,5785.03) 997.54,5785.03 cw(c1092.51,5785.03) J15.5@1025.36,5852.18 ; J15.5@972.55,5855.01 cw(c912.22,5794.69) 997.54,5794.69 cw(c1082.85,5794.69) J15.5@1022.53,5855.01 ; J15.5@975.38,5857.84 cw(c921.88,5804.34) 997.54,5804.34 cw(c1073.2,5804.34) J15.5@1019.7,5857.84 ; J15.5@978.21,5860.67 cw(c931.54,5814) 997.54,5814 cw(c1063.54,5814) J15.5@1016.87,5860.67 ; J15.5@981.04,5863.5 cw(c941.19,5823.66) 997.54,5823.66 cw(c1053.88,5823.66) J15.5@1014.04,5863.5 ; J15.5@983.86,5866.33 cw(c950.85,5833.31) 997.54,5833.31 cw(c1044.23,5833.31) J15.5@1011.21,5866.33 ; J15.5@997.54,5880 997.54,5442.54 987.5,5432.5 352.5,5432.5
ATE.HOST_ID.DATA: D7.2 R131.1 R132.2 U30.A14 | length 3141.1
  Top Layer w4: v1(8124.52,2650.04) 8209.96,2650.04 8239.19,2620.81 v1(8239.19,2518.04) ; v1@8128.41,2646.15 cw(c8137.8,2636.76) 8137.8,2650.04 cw(c8137.8,2663.32) v1@8128.41,2653.93 ; v1@8131.24,2643.32 cw(c8147.46,2627.11) 8147.46,2650.04 cw(c8147.46,2672.98) v1@8131.24,2656.76 ; v1@8232.47,2524.76 ccw(c8216.26,2540.98) 8239.19,2540.98 ccw(c8262.13,2540.98) v1@8245.91,2524.76 ; v1@8235.3,2521.93 ccw(c8225.91,2531.32) 8239.19,2531.32 ccw(c8252.47,2531.32) v1@8243.08,2521.93
  Top Layer w8: U30.A14@7384.02,1721.36 cw(c7384.02,1707.26) 7393.99,1717.23 cw(c7403.96,1727.2) U30.A14@7389.86,1727.2 ; U30.A14@7384.02,1727.2 v2(7403.7,1707.52) ; v2@7394.7,1707.52 ccw(c7372.97,1707.52) 7388.34,1722.88 ccw(c7403.7,1738.25) v2@7403.7,1716.52
  MidLayer1 w4: v1@8232.47,2511.32 cw(c8214.64,2493.5) 8239.86,2493.5 ; v1@8235.3,2514.15 cw(c8224.3,2503.15) 8239.86,2503.15 ; v1(8239.19,2518.04) 8239.86,2517.37 8239.86,2158.71 v1(8281.86,2116.71) ; 8239.86,2496.72 cw(c8260.51,2496.72) v1@8245.91,2511.32 ; 8239.86,2506.37 cw(c8250.86,2506.37) v1@8243.08,2514.15 ; v1@8272.36,2116.71 ccw(c8249.42,2116.71) 8265.64,2132.93 ccw(c8281.86,2149.14) v1@8281.86,2126.21 ; v1@8276.36,2116.71 ccw(c8263.08,2116.71) 8272.47,2126.1 ccw(c8281.86,2135.49) v1@8281.86,2122.21
  MidLayer2 w4: v2(7403.7,1707.52) 7744.11,1707.52 7748.52,1703.11 8260.92,1703.11 8297.81,1740 8297.81,2100.75 ; v2@7408.65,1702.57 cw(c7420.6,1690.62) 7420.6,1707.52 cw(c7420.6,1724.42) v2@7408.65,1712.47 ; v2@7411.48,1699.74 cw(c7430.26,1680.96) 7430.26,1707.52 cw(c7430.26,1734.08) v2@7411.48,1715.3 ; v1(8281.86,2116.71) 8297.81,2100.75 ; v1@8281.92,2111.21 cw(c8282.07,2098.45) 8291.09,2107.47 cw(c8300.12,2116.49) v1@8287.36,2116.64 ; v1@8281.97,2107.21 cw(c8282.23,2085.17) 8297.81,2100.75 ; v1@8291.36,2116.6 ccw(c8313.39,2116.34) 8297.81,2100.75
  Bottom Layer w4: R132.2@8073.82,2620 8093.05,2639.23 8103.86,2650.04 ; R132.2@8073.82,2625.81 ccw(c8073.82,2639.83) R132.2@8083.73,2629.92 ; R132.2@8073.82,2629.81 ccw(c8073.82,2653.49) 8090.56,2636.75 ; R132.2@8079.14,2620.49 cw(c8090.8,2620.49) R132.2@8082.55,2628.74 ; R132.2@8083.14,2620.49 cw(c8104.45,2620.49) 8089.38,2635.56 ; D7.2@8083.89,2826.12 cw(c8057.06,2799.28) 8095,2799.28 cw(c8132.94,2799.29) D7.2@8106.11,2826.12 ; D7.2@8086.72,2828.94 cw(c8066.71,2808.94) 8095,2808.94 cw(c8123.29,2808.94) D7.2@8103.28,2828.94 ; D7.2@8089.54,2831.77 cw(c8076.37,2818.6) 8095,2818.6 cw(c8113.63,2818.6) D7.2@8100.46,2831.77 ; D7.2@8095,2838.21 8095,2724.62 8124.52,2695.09 v1(8124.52,2650.04) 8103.86,2650.04 ; R131.1@8116.18,2510 8133.23,2510 ; v1@8117.31,2643.86 ccw(c8103.86,2632.31) 8103.86,2650.04 ; v1@8117.31,2656.23 cw(c8103.86,2667.77) 8103.86,2650.04 ; v1@8117.81,2656.76 ccw(c8101.59,2672.98) 8124.52,2672.98 ccw(c8147.46,2672.98) v1@8131.24,2656.76 ; v1@8120.35,2646.46 ccw(c8112.56,2639.78) 8112.56,2650.04 ccw(c8112.56,2660.3) v1@8120.35,2653.62 ; v1@8120.64,2653.93 ccw(c8111.25,2663.32) 8124.52,2663.32 ccw(c8137.8,2663.32) v1@8128.41,2653.93 ; R131.1@8124.02,2504.97 cw(c8133.23,2499.06) 8133.23,2510 ; R131.1@8124.02,2515.03 ccw(c8133.23,2520.94) 8133.23,2510 ; v1@8232.47,2511.32 ccw(c8216.26,2495.11) 8216.26,2518.04 ccw(c8216.26,2540.98) v1@8232.47,2524.76 ; v1@8235.3,2514.15 ccw(c8225.91,2504.76) 8225.91,2518.04 ccw(c8225.91,2531.32) v1@8235.3,2521.93 ; v1(8239.19,2518.04) 8141.27,2518.04 8133.23,2510
ATE.HOST_ID.EXT_PROG: J33.B40 R132.1 U23.2 | length 14798.7
  Top Layer w4: U23.2@8091.37,2603.08 ccw(c8072.94,2621.51) 8099,2621.51 ; U23.2@8094.19,2600.25 ccw(c8082.59,2611.85) 8099,2611.85 ccw(c8115.4,2611.85) U23.2@8103.8,2600.25 ; U23.2@8099,2572.81 8099,2621.51 ; 8099,2624.52 8099,2621.51 ; U23.2@8106.63,2603.08 cw(c8125.06,2621.51) 8099,2621.51 ; v1@8184.99,2664.99 ccw(c8168.77,2648.77) 8168.77,2671.71 ccw(c8168.77,2694.64) v1@8184.99,2678.43 ; v1@8187.82,2667.82 ccw(c8178.43,2658.43) 8178.43,2671.71 ccw(c8178.43,2684.99) v1@8187.82,2675.6 ; v1(8191.71,2671.71) 8106.71,2671.71 8099,2664 8099,2621.51
  MidLayer1 w4: v1(695,1910) 840,1910 860,1890 860,1639.75 1067.25,1432.5 1162.25,1432.5 1202.71,1392.04 2642.96,1392.04 2698.52,1336.48 v1(2698.52,100.04) ; v1@698.89,1906.11 cw(c708.28,1896.72) 708.28,1910 cw(c708.28,1923.28) v1@698.89,1913.89 ; v1@701.72,1903.28 cw(c717.93,1887.06) 717.93,1910 cw(c717.93,1932.93) v1@701.72,1916.72 ; v1@2691.81,106.76 ccw(c2675.59,122.98) 2698.52,122.98 ccw(c2721.46,122.98) v1@2705.24,106.76 ; v1@2694.64,103.93 ccw(c2685.25,113.32) 2698.52,113.32 ccw(c2711.8,113.32) v1@2702.41,103.93 ; 5359.96,325.04 v1(5198.52,325.04) 5374.96,325.04 5390,310 5630.63,310 5655.63,335 5810,335 5900,245 6265,245 6393.29,116.71 7456.71,116.71 7662.02,322.02 7662.02,1265.91 7879.82,1483.71 8183.31,1483.71 8258,1558.39 8258,1686.69 8318,1746.69 8318,2105.56 8247.86,2175.71 8247.86,2496 8256.86,2505 8256.86,2648.14 8233.29,2671.71 v1(8191.71,2671.71) ; v1@8195.6,2667.82 cw(c8204.99,2658.43) 8204.99,2671.71 cw(c8204.99,2684.99) v1@8195.6,2675.6 ; v1@8198.43,2664.99 cw(c8214.64,2648.77) 8214.64,2671.71 cw(c8214.64,2694.64) v1@8198.43,2678.43
  MidLayer2 w4: v1@-665,2611.5 cw(c-665,2588.56) -648.78,2604.78 cw(c-632.57,2621) v1@-655.5,2621 ; v1@-665,2615.5 cw(c-665,2602.22) -655.61,2611.61 cw(c-646.22,2621) v1@-659.5,2621 ; v1(-665,2621) -595,2551 -595,2463.23 -581.48,2449.71 -568.35,2449.71 -452.02,2333.37 -328.37,2333.37 -272,2277 -272,2178.44 -257.27,2163.71 -106.61,2163.71 -88.31,2182 -55.69,2182 -30.69,2157 124.31,2157 371.31,1910 v1(695,1910) ; v1@688.28,1903.28 ccw(c672.06,1887.06) 672.06,1910 ccw(c672.06,1932.93) v1@688.28,1916.72 ; v1@691.11,1906.11 ccw(c681.72,1896.72) 681.72,1910 ccw(c681.72,1923.28) v1@691.11,1913.89
  Bottom Layer w4: J33.B40@-785.98,2652.86 -704.49,2652.86 -685,2633.37 -678.81,2633.37 -666.44,2621 v1(-665,2621) ; J33.B40@-717.1,2653.08 cw(c-715.31,2627.69) -697.31,2645.69 ; J33.B40@-716.82,2649.09 cw(c-714.5,2616.09) -691.11,2639.48 ; J33.B40@-716.54,2645.1 cw(c-713.68,2604.5) -684.91,2633.28 ; v1@2698.52,90.54 cw(c2698.52,67.61) 2714.74,83.82 cw(c2730.96,100.04) v1@2708.02,100.04 ; v1@2698.52,94.54 cw(c2698.52,81.26) 2707.91,90.65 cw(c2717.3,100.04) v1@2704.02,100.04 ; v1(2698.52,100.04) 2743.56,55 3895,55 4081.37,241.37 4601.37,241.37 4655.19,295.19 5095.19,295.19 5145,345 5178.56,345 v1(5198.52,325.04) ; R132.1@8116.18,2620 8175,2620 8191.71,2636.71 v1(8191.71,2671.71) ; v1@8184.99,2664.99 cw(c8168.77,2648.77) 8191.71,2648.77 cw(c8214.64,2648.77) v1@8198.43,2664.99 ; v1@8187.82,2667.82 cw(c8178.43,2658.43) 8191.71,2658.43 cw(c8204.99,2658.43) v1@8195.6,2667.82
ATE.HOST_JTAG.HARD.TCK: J25.3 J33.B1 R269.1 | length 13221.2
  Top Layer w4: J25.3@7586.08,5457.35 cw(c7610.33,5467.92) 7591.62,5486.62 ; J25.3@7586.99,5420.25 7586.99,5481.99 7616.53,5511.53 ; J25.3@7589.74,5458.95 cw(c7616.11,5470.44) 7595.77,5490.77 ; J25.3@7593.41,5460.55 cw(c7621.9,5472.96) 7599.93,5494.93 ; J25.3@7597.08,5462.15 cw(c7627.68,5475.48) 7604.08,5499.08 ; J25.3@7600.75,5463.74 cw(c7633.46,5477.99) 7608.23,5503.23 ; J25.3@7604.41,5465.34 cw(c7639.24,5480.51) 7612.38,5507.38 ; J25.3@7608.08,5466.94 cw(c7645.03,5483.03) 7616.53,5511.53 ; v1@7863.1,5836.29 ccw(c7846.88,5820.07) 7846.88,5843 ccw(c7846.88,5865.94) v1@7863.1,5849.72 ; v1@7865.93,5839.11 ccw(c7856.54,5829.73) 7856.54,5843 ccw(c7856.54,5856.28) v1@7865.93,5846.89 ; v1@7873.7,5839.11 cw(c7883.09,5829.73) 7883.09,5843 cw(c7883.09,5856.28) v1@7873.7,5846.89 ; v1@7876.53,5836.29 cw(c7892.75,5820.07) 7892.75,5843 cw(c7892.75,5865.94) v1@7876.53,5849.72 ; v1@7877.27,5843 ccw(c7877.27,5874.05) R269.1@7899.22,5852.1 ; 7886.93,5843 ccw(c7886.93,5864.39) R269.1@7902.05,5849.27 ; 7889.36,5843 cw(c7889.36,5829.06) R269.1@7899.22,5838.92 ; R269.1@7905.81,5846 7902.82,5843 v1(7869.82,5843) 7748,5843 7734.41,5829.41 7734.41,5567.64 7678.3,5511.53 7616.53,5511.53
  MidLayer1 w4: v4@5010,6790.19 cw(c5010,6766.5) 5026.75,6783.25 cw(c5043.5,6800) v4@5019.81,6800 ; v4@5010,6794.19 cw(c5010,6780.16) 5019.92,6790.08 cw(c5029.84,6800) v4@5015.81,6800 ; v4(5010,6800) 5047,6763 7382,6763 7424,6721 7424,6439.63 7462.85,6400.78 7462.85,6269.78 7528.73,6203.9 7605.37,6203.9 7869.82,5939.46 v1(7869.82,5843) ; v1@7863.1,5849.72 ccw(c7846.88,5865.94) 7869.82,5865.94 ccw(c7892.75,5865.94) v1@7876.53,5849.72 ; v1@7865.93,5846.89 ccw(c7856.54,5856.28) 7869.82,5856.28 ccw(c7883.09,5856.28) v1@7873.7,5846.89
  Bottom Layer w4: J33.B1@-785.98,4267.03 -700,4267.03 ; J33.B1@-706.07,4262.85 cw(c-700,4260.54) -700,4267.03 ; J33.B1@-706.07,4271.22 ccw(c-700,4273.53) -700,4267.03 ; v4@5000.19,6800 cw(c4976.5,6800) 4993.25,6783.25 cw(c5010,6766.5) v4@5010,6790.19 ; v4@5004.19,6800 cw(c4990.16,6800) 5000.08,6790.08 cw(c5010,6780.16) v4@5010,6794.19 ; v4(5010,6800) 4943.04,6733.04 2856.96,6733.04 2780,6810 389.5,6810 99.5,6520 80,6520 55,6495 55,6465.19 90.52,6429.67 90.52,6278.36 -129.83,6058 -236.5,6058 -270.21,6091.71 -556.81,6091.71 -568.48,6080.04 -568.48,5806.52 -615,5760 -644.81,5760 -662,5742.81 -662,5342 -651.15,5331.15 -615,5295 -615,4616.86 -567.65,4569.5 -567.65,4229.35 -580.29,4216.71 -665.39,4216.71 -683.26,4234.57 -684.32,4234.57 -692.5,4242.75 -692.5,4259.53 -700,4267.03
ATE.HOST_JTAG.HARD.TDI: J25.1 J33.B2 R267.1 | length 14292
  Top Layer w4: v4(85,6150) 110,6175 v4(110,6600) ; v4@85,6155.81 ccw(c85,6169.84) 94.92,6159.92 ccw(c104.84,6150) v4@90.81,6150 ; v4@85,6159.81 ccw(c85,6183.5) 101.75,6166.75 ccw(c118.5,6150) v4@94.81,6150 ; v4@103.06,6593.06 cw(c86.31,6576.31) 110,6576.31 cw(c133.69,6576.31) v4@116.94,6593.06 ; v4@105.89,6595.89 cw(c95.97,6585.97) 110,6585.97 cw(c124.03,6585.97) v4@114.11,6595.89 ; J25.1@7470.73,5403.99 ccw(c7431.47,5364.73) 7431.47,5420.25 ccw(c7431.47,5475.78) J25.1@7470.73,5436.52 ; J25.1@7473.56,5406.82 ccw(c7441.12,5374.38) 7441.12,5420.25 ccw(c7441.12,5466.12) J25.1@7473.56,5433.69 ; J25.1@7476.39,5409.65 ccw(c7450.78,5384.04) 7450.78,5420.25 ccw(c7450.78,5456.47) J25.1@7476.39,5430.86 ; J25.1@7479.21,5412.47 ccw(c7460.44,5393.7) 7460.44,5420.25 ccw(c7460.44,5446.81) J25.1@7479.21,5428.03 ; J25.1@7484.97,5480.66 ccw(c7484.77,5482.87) 7486.99,5482.87 ; J25.1@7489.02,5480.66 cw(c7489.21,5482.87) 7486.99,5482.87 ; v4@7528.06,5853.06 cw(c7511.31,5836.31) 7535,5836.31 cw(c7558.69,5836.31) v4@7541.94,5853.06 ; v4@7530.89,5855.89 cw(c7520.97,5845.97) 7535,5845.97 cw(c7549.03,5845.97) v4@7539.11,5855.89 ; v4(7535,5860) 7535,5771.92 7508.08,5745 7430,5745 7415,5730 7415,5430 7424.75,5420.25 J25.1@7486.99,5420.25 7486.99,5482.87 ; v4(7854,5997) R267.1@7905.81,5997 ; v4@7858.11,5992.89 cw(c7868.03,5982.97) 7868.03,5997 cw(c7868.03,6011.03) v4@7858.11,6001.11 ; v4@7860.94,5990.06 cw(c7877.69,5973.31) 7877.69,5997 cw(c7877.69,6020.69) v4@7860.94,6003.94 ; R267.1@7899.22,5990.41 ccw(c7883.31,5974.5) 7883.31,5997 ccw(c7883.31,6019.5) R267.1@7899.22,6003.59 ; R267.1@7902.05,5993.24 ccw(c7892.97,5984.16) 7892.97,5997 ccw(c7892.97,6009.84) R267.1@7902.05,6000.76
  MidLayer1 w4: v4(-510,4760) -524.14,4774.14 -524.14,5258.23 -454.81,5327.56 -329.09,5327.56 -311.52,5345.14 -311.52,5905.86 -184.56,6032.81 -47.62,6032.81 -35,6020.19 v4(-35,5990) ; v4@-41.94,5996.94 ccw(c-58.69,6013.69) -35,6013.69 ccw(c-11.31,6013.69) v4@-28.06,5996.94 ; v4@-39.11,5994.11 ccw(c-49.03,6004.03) -35,6004.03 ccw(c-20.97,6004.03) v4@-30.89,5994.11 ; v4@103.06,6606.94 ccw(c86.31,6623.69) 110,6623.69 ccw(c133.69,6623.69) v4@116.94,6606.94 ; v4@105.89,6604.11 ccw(c95.97,6614.03) 110,6614.03 ccw(c124.03,6614.03) v4@114.11,6604.11 ; v4(110,6600) 110,6770 218.28,6878.28 4865.41,6878.28 4996.69,6747 7375.37,6747 7408,6714.37 7408,6433 7446.85,6394.15 7446.85,6263.15 7600,6110 7600,5875 7585,5860 ; v4(7535,5860) 7585,5860 ; v4@7539.11,5855.89 cw(c7549.03,5845.97) 7549.03,5860 cw(c7549.03,5874.03) v4@7539.11,5864.11 ; v4@7541.94,5853.06 cw(c7558.69,5836.31) 7558.69,5860 cw(c7558.69,5883.69) v4@7541.94,5866.94 ; v4@7854,5987.19 cw(c7854,5963.5) 7870.75,5980.25 cw(c7887.5,5997) v4@7863.81,5997 ; v4@7854,5991.19 cw(c7854,5977.16) 7863.92,5987.08 cw(c7873.84,5997) v4@7859.81,5997 ; v4(7854,5997) 7889.81,5961.19 7906.62,5961.19 7942.81,5925 7942.81,5822.81 7929,5809 7823,5809 7796,5836 7751,5836 7737,5822 7623,5822 7585,5860
  MidLayer2 w4: v4(-595,4760) v4(-510,4760) ; v4@-590.89,4755.89 cw(c-580.97,4745.97) -580.97,4760 cw(c-580.97,4774.03) v4@-590.89,4764.11 ; v4@-588.06,4753.06 cw(c-571.31,4736.31) -571.31,4760 cw(c-571.31,4783.69) v4@-588.06,4766.94 ; v4@-516.94,4753.06 ccw(c-533.69,4736.31) -533.69,4760 ccw(c-533.69,4783.69) v4@-516.94,4766.94 ; v4@-514.11,4755.89 ccw(c-524.03,4745.97) -524.03,4760 ccw(c-524.03,4774.03) v4@-514.11,4764.11 ; v4@-41.94,5996.94 ccw(c-58.69,6013.69) -35,6013.69 ccw(c-11.31,6013.69) v4@-28.06,5996.94 ; v4@-39.11,5994.11 ccw(c-49.03,6004.03) -35,6004.03 ccw(c-20.97,6004.03) v4@-30.89,5994.11 ; v4(-35,5990) -35,6030 v4(85,6150) ; v4@75.19,6150 cw(c51.5,6150) 68.25,6133.25 cw(c85,6116.5) v4@85,6140.19 ; v4@79.19,6150 cw(c65.16,6150) 75.08,6140.08 cw(c85,6130.16) v4@85,6144.19
  Bottom Layer w4: J33.B2@-785.98,4227.66 -782.82,4224.5 -684.5,4224.5 -668.71,4208.71 -576.98,4208.71 -559.65,4226.04 -559.65,4724.65 v4(-595,4760) ; J33.B2@-714.22,4230.13 ccw(c-701.94,4240.7) -701.94,4224.5 ; J33.B2@-711.19,4232.74 ccw(c-693.22,4248.21) -693.22,4224.5 ; J33.B2@-708.76,4219.33 cw(c-696.29,4206.86) -696.29,4224.5 ; J33.B2@-708.16,4235.35 ccw(c-684.5,4255.71) -684.5,4224.5 ; v4@-595,4750.19 cw(c-595,4726.5) -578.25,4743.25 cw(c-561.5,4760) v4@-585.19,4760 ; v4@-595,4754.19 cw(c-595,4740.16) -585.08,4750.08 cw(c-575.16,4760) v4@-589.19,4760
